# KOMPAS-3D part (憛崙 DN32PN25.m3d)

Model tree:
1. Объединить компоненты:1  (labels: СЕНС DN32PN25)

Referenced files in D:\Савин\!СЕНСОР\3D для заказчика\!Новый перечень\СЕНС\1. СЕНС\DN32\: СЕНС DN32PN25.a3d
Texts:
  СЕНС DN32PN25
  ООО НПП Сенсор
